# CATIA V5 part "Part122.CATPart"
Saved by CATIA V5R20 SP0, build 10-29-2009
Part number: FA 084700-3
Revision: ANY
Definition: UNKNOWN
Nomenclature: FA 084700-3
Source: Unknown
Bounding box of the stored display mesh (mm): x -2.687 to 2.687, y -2.475 to 2.475, z -2.5 to 2.5
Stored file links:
  C:\Users\Utente\Desktop\IO LAVORO\3D X SITO CF\CUMSA\3D files FA\FA 084705-20\Part122.CATPart

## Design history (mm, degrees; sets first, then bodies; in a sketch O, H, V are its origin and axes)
Body1 "Chaflán4" (main body)
  Solid1: solid without history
